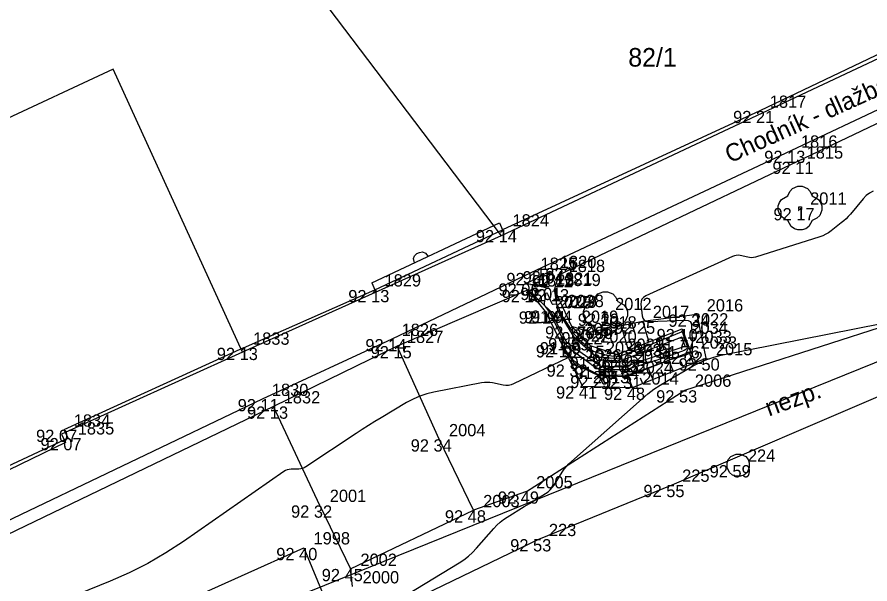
# Model space of a CAD drawing. Extents: x -711081 to -709338, y -1025122 to -1024092.
# Drawn here: x -710758.72 to -710739.27, y -1024920.86 to -1024907.92 of the extents above; entities that cross this region are included whole.
import ezdxf

# ---------------------------------------------------------------- set-up
doc = ezdxf.new("R2010")
doc.units = 0
for name, color, linetype in [('Ex_Major Contours', 7, 'Continuous'), ('Ex_Minor Contours', 7, 'Continuous'), ('Z_betonova_konstrukce', 7, 'Continuous'), ('Z_body', 7, 'Continuous'), ('Z_body_cisla', 7, 'Continuous'), ('Z_body_vysky_redukovane', 7, 'Continuous'), ('Z_budova', 7, 'Continuous'), ('Z_chodnik', 7, 'Continuous'), ('Z_hrany_paty', 7, 'Continuous'), ('Z_katastr_cisla_stavebni', 7, 'Continuous'), ('Z_katastr_hranice', 7, 'Continuous'), ('Z_katastr_vnitrni_kresba', 7, 'Continuous'), ('Z_komunikace', 7, 'Continuous'), ('Z_ploty', 7, 'Continuous'), ('Z_ploty_znacky', 7, 'Continuous'), ('Z_popisy', 7, 'Continuous'), ('Z_rozhranni', 7, 'Continuous'), ('Z_site_kanalizace_znaky', 7, 'Continuous'), ('Z_technicke_srafy', 7, 'Continuous'), ('Z_vstupy', 7, 'Continuous'), ('Z_zelen_jednotliva', 7, 'Continuous'), ('Z_zelen_obvod', 7, 'Continuous'), ('Z_zlabek', 7, 'Continuous')]:
    doc.layers.add(name, color=color, linetype=linetype)

# ---------------------------------------------------------------- blocks, each defined once
blk = doc.blocks.new('POINT_DISPLAY')
blk.add_line((0, 0), (0, 0))
blk = doc.blocks.new('Z24')
for p, q in [((-0.23, 0.38), (-0.17, 0.45)), ((-0.17, 0.45), (-0.05, 0.5)), ((-0.05, 0.5), (0.05, 0.5)), ((0.05, 0.5), (0.17, 0.45)), ((0.17, 0.45), (0.23, 0.38)), ((-0.47, 0.13), (-0.42, 0.2)), ((-0.42, 0.2), (-0.28, 0.28)), ((-0.28, 0.28), (-0.23, 0.38)), ((0.23, 0.38), (0.28, 0.28)), ((0.28, 0.28), (0.42, 0.2)), ((0.42, 0.2), (0.47, 0.13)), ((-0.5, 0.05), (-0.47, 0.13)), ((-0.5, -0.05), (-0.5, 0.05)), ((-0.03, -0.03), (-0.03, 0.03)), ((-0.03, 0.03), (0.03, 0.03)), ((0.03, 0.03), (0.03, -0.03)), ((0.47, 0.13), (0.5, 0.05)), ((0.5, 0.05), (0.5, -0.05)), ((-0.45, -0.17), (-0.5, -0.05)), ((-0.38, -0.23), (-0.45, -0.17)), ((0.03, -0.03), (-0.03, -0.03)), ((0.45, -0.17), (0.38, -0.23)), ((0.5, -0.05), (0.45, -0.17)), ((-0.28, -0.28), (-0.38, -0.23)), ((-0.2, -0.42), (-0.28, -0.28)), ((0.28, -0.28), (0.2, -0.42)), ((0.38, -0.23), (0.28, -0.28)), ((-0.13, -0.47), (-0.2, -0.42)), ((-0.05, -0.5), (-0.13, -0.47)), ((0.05, -0.5), (-0.05, -0.5)), ((0.13, -0.47), (0.05, -0.5)), ((0.2, -0.42), (0.13, -0.47))]:
    blk.add_line(p, q)
blk = doc.blocks.new('Z216')
for p, q in [((-0.17, 0), (-0.15, 0.1)), ((-0.15, 0.1), (-0.1, 0.15)), ((-0.1, 0.15), (-0.03, 0.17)), ((-0.03, 0.17), (0.03, 0.17)), ((0.03, 0.17), (0.1, 0.15)), ((0.1, 0.15), (0.15, 0.1)), ((0.15, 0.1), (0.17, 0))]:
    blk.add_line(p, q)
blk = doc.blocks.new('Z620')
for p, q in [((-0.23, 0.13), (-0.17, 0.2)), ((-0.17, 0.2), (-0.05, 0.25)), ((-0.05, 0.25), (0.05, 0.25)), ((0.05, 0.25), (0.17, 0.2)), ((0.17, 0.2), (0.23, 0.13)), ((-0.25, 0.05), (-0.23, 0.13)), ((-0.25, -0.05), (-0.25, 0.05)), ((0.23, 0.13), (0.25, 0.05)), ((0.25, 0.05), (0.25, -0.05)), ((-0.2, -0.17), (-0.25, -0.05)), ((-0.13, -0.23), (-0.2, -0.17)), ((0.2, -0.17), (0.13, -0.23)), ((0.25, -0.05), (0.2, -0.17)), ((-0.05, -0.25), (-0.13, -0.23)), ((0.05, -0.25), (-0.05, -0.25)), ((0.13, -0.23), (0.05, -0.25))]:
    blk.add_line(p, q)

msp = doc.modelspace()

# ---------------------------------------------------------------- linework, layer by layer
at = {"layer": 'Ex_Major Contours'}
msp.add_lwpolyline([(-710745.611, -1024915.523), (-710745.573, -1024915.546), (-710745.533, -1024915.564), (-710745.491, -1024915.577), (-710745.293, -1024915.629), (-710745.261, -1024915.636), (-710745.23, -1024915.642), (-710745.197, -1024915.647), (-710745.165, -1024915.65), (-710745.036, -1024915.66), (-710745.003, -1024915.66), (-710744.972, -1024915.657), (-710744.941, -1024915.651), (-710744.91, -1024915.641), (-710744.161, -1024915.347), (-710744.1, -1024915.323), (-710744.039, -1024915.299), (-710743.978, -1024915.274), (-710743.917, -1024915.249), (-710743.567, -1024915.104), (-710743.561, -1024915.102), (-710743.555, -1024915.103), (-710743.551, -1024915.106), (-710743.547, -1024915.112), (-710743.535, -1024915.14), (-710743.532, -1024915.148), (-710743.53, -1024915.155), (-710743.527, -1024915.162), (-710743.525, -1024915.169), (-710743.445, -1024915.412), (-710743.438, -1024915.452), (-710743.446, -1024915.484), (-710743.467, -1024915.51), (-710743.502, -1024915.529), (-710743.9, -1024915.676), (-710743.98, -1024915.705), (-710744.061, -1024915.733), (-710744.142, -1024915.76), (-710744.224, -1024915.786), (-710744.789, -1024915.961), (-710744.816, -1024915.969), (-710744.844, -1024915.974), (-710744.871, -1024915.977), (-710744.9, -1024915.977), (-710745.013, -1024915.976), (-710745.041, -1024915.975), (-710745.07, -1024915.975), (-710745.098, -1024915.974), (-710745.126, -1024915.974), (-710745.369, -1024915.972), (-710745.393, -1024915.97), (-710745.416, -1024915.966), (-710745.438, -1024915.959), (-710745.46, -1024915.95), (-710745.545, -1024915.906), (-710745.567, -1024915.895), (-710745.587, -1024915.882), (-710745.607, -1024915.869), (-710745.627, -1024915.855), (-710746.112, -1024915.491), (-710746.125, -1024915.48), (-710746.137, -1024915.469), (-710746.149, -1024915.457), (-710746.16, -1024915.444), (-710746.203, -1024915.393), (-710746.213, -1024915.379), (-710746.222, -1024915.365), (-710746.231, -1024915.351), (-710746.239, -1024915.336), (-710746.459, -1024914.874), (-710746.471, -1024914.85), (-710746.483, -1024914.825), (-710746.496, -1024914.801), (-710746.508, -1024914.777), (-710746.565, -1024914.672), (-710746.576, -1024914.653), (-710746.588, -1024914.634), (-710746.6, -1024914.616), (-710746.613, -1024914.598), (-710746.668, -1024914.528), (-710746.68, -1024914.51), (-710746.687, -1024914.491), (-710746.69, -1024914.47), (-710746.689, -1024914.449), (-710746.657, -1024914.255), (-710746.65, -1024914.225), (-710746.64, -1024914.214), (-710746.628, -1024914.222), (-710746.614, -1024914.25), (-710746.532, -1024914.447), (-710746.526, -1024914.458), (-710746.517, -1024914.465), (-710746.507, -1024914.47), (-710746.494, -1024914.47), (-710746.439, -1024914.467), (-710746.427, -1024914.468), (-710746.416, -1024914.472), (-710746.408, -1024914.48), (-710746.401, -1024914.491), (-710746.333, -1024914.652), (-710746.319, -1024914.682), (-710746.304, -1024914.713), (-710746.287, -1024914.742), (-710746.27, -1024914.771), (-710746.062, -1024915.091), (-710746.044, -1024915.117), (-710746.025, -1024915.142), (-710746.005, -1024915.166), (-710745.984, -1024915.188), (-710745.896, -1024915.277), (-710745.874, -1024915.299), (-710745.851, -1024915.321), (-710745.828, -1024915.342), (-710745.804, -1024915.362), (-710745.646, -1024915.496)], close=True, dxfattribs=at)
at = {"layer": 'Ex_Minor Contours'}
for points in [[(-710739.192, -1024911.897), (-710739.277, -1024911.939), (-710739.353, -1024911.995), (-710739.422, -1024912.066), (-710739.711, -1024912.417), (-710739.759, -1024912.472), (-710739.81, -1024912.524), (-710739.864, -1024912.573), (-710739.92, -1024912.62), (-710740.151, -1024912.801), (-710740.21, -1024912.843), (-710740.272, -1024912.879), (-710740.337, -1024912.91), (-710740.406, -1024912.935), (-710741.88, -1024913.397), (-710741.923, -1024913.407), (-710741.966, -1024913.412), (-710742.01, -1024913.411), (-710742.054, -1024913.404), (-710742.23, -1024913.364), (-710742.273, -1024913.358), (-710742.316, -1024913.359), (-710742.358, -1024913.367), (-710742.4, -1024913.382), (-710744.382, -1024914.287), (-710744.434, -1024914.319), (-710744.469, -1024914.361), (-710744.488, -1024914.413), (-710744.49, -1024914.474), (-710744.463, -1024914.738), (-710744.449, -1024914.795), (-710744.42, -1024914.836), (-710744.376, -1024914.859), (-710744.317, -1024914.866), (-710743.466, -1024914.838), (-710743.41, -1024914.844), (-710743.369, -1024914.867), (-710743.343, -1024914.906), (-710743.334, -1024914.962), (-710743.324, -1024915.29), (-710743.323, -1024915.319), (-710743.323, -1024915.348), (-710743.322, -1024915.376), (-710743.322, -1024915.405), (-710743.322, -1024915.524), (-710743.325, -1024915.548), (-710743.333, -1024915.568), (-710743.348, -1024915.584), (-710743.369, -1024915.596), (-710743.465, -1024915.635), (-710743.489, -1024915.644), (-710743.513, -1024915.653), (-710743.537, -1024915.661), (-710743.562, -1024915.669), (-710743.761, -1024915.726), (-710743.802, -1024915.738), (-710743.843, -1024915.752), (-710743.884, -1024915.765), (-710743.924, -1024915.78), (-710744.628, -1024916.04), (-710744.646, -1024916.047), (-710744.665, -1024916.053), (-710744.684, -1024916.059), (-710744.703, -1024916.065), (-710744.779, -1024916.089), (-710744.798, -1024916.094), (-710744.817, -1024916.098), (-710744.836, -1024916.1), (-710744.856, -1024916.1), (-710745.386, -1024916.092), (-710745.41, -1024916.091), (-710745.433, -1024916.091), (-710745.439, -1024916.091), (-710745.445, -1024916.09), (-710745.451, -1024916.088), (-710745.456, -1024916.085), (-710745.869, -1024915.875), (-710745.885, -1024915.866), (-710745.901, -1024915.856), (-710745.917, -1024915.846), (-710745.932, -1024915.835), (-710745.992, -1024915.79), (-710746.007, -1024915.778), (-710746.021, -1024915.765), (-710746.034, -1024915.752), (-710746.046, -1024915.738), (-710746.124, -1024915.643), (-710746.129, -1024915.638), (-710746.133, -1024915.637), (-710746.135, -1024915.64), (-710746.136, -1024915.647), (-710746.139, -1024915.68), (-710746.14, -1024915.687), (-710746.143, -1024915.694), (-710746.148, -1024915.699), (-710746.155, -1024915.703), (-710747.396, -1024916.296), (-710747.453, -1024916.319), (-710747.512, -1024916.331), (-710747.571, -1024916.333), (-710747.632, -1024916.324), (-710747.878, -1024916.272), (-710747.94, -1024916.262), (-710748.001, -1024916.259), (-710748.063, -1024916.261), (-710748.124, -1024916.27), (-710749.213, -1024916.485), (-710749.376, -1024916.525), (-710749.535, -1024916.578), (-710749.688, -1024916.644), (-710749.836, -1024916.723), (-710750.419, -1024917.067), (-710750.564, -1024917.154), (-710750.708, -1024917.243), (-710750.85, -1024917.333), (-710750.991, -1024917.426), (-710752.133, -1024918.188), (-710752.171, -1024918.21), (-710752.211, -1024918.226), (-710752.252, -1024918.235), (-710752.296, -1024918.239), (-710752.474, -1024918.244), (-710752.518, -1024918.248), (-710752.559, -1024918.258), (-710752.599, -1024918.274), (-710752.636, -1024918.296), (-710754.926, -1024919.89), (-710755.327, -1024920.153), (-710755.74, -1024920.392), (-710756.165, -1024920.607), (-710756.603, -1024920.8), (-710761.026, -1024922.594)], [(-710750.578, -1024921.561), (-710748.641, -1024920.383), (-710748.531, -1024920.31), (-710748.427, -1024920.229), (-710748.33, -1024920.141), (-710748.239, -1024920.045), (-710747.846, -1024919.595), (-710747.778, -1024919.523), (-710747.704, -1024919.455), (-710747.626, -1024919.394), (-710747.543, -1024919.339), (-710747.151, -1024919.097), (-710747.03, -1024919.023), (-710746.909, -1024918.948), (-710746.667, -1024918.799), (-710746.61, -1024918.759), (-710746.558, -1024918.714), (-710746.512, -1024918.662), (-710746.471, -1024918.605), (-710746.285, -1024918.311), (-710746.239, -1024918.243), (-710746.189, -1024918.18), (-710746.134, -1024918.12), (-710746.075, -1024918.064), (-710744.464, -1024916.635), (-710744.331, -1024916.523), (-710744.194, -1024916.418), (-710744.051, -1024916.321), (-710743.903, -1024916.231), (-710743.301, -1024915.883), (-710743.148, -1024915.803), (-710742.99, -1024915.736), (-710742.827, -1024915.683), (-710742.659, -1024915.642), (-710739.003, -1024914.918)]]:
    msp.add_lwpolyline(points, dxfattribs=at)
at = {"layer": 'Z_betonova_konstrukce'}
for p, q in [((-710746.67, -1024914.64), (-710747.06, -1024914.15)), ((-710746.55, -1024914.63), (-710747.06, -1024914.15)), ((-710746.07, -1024914.98), (-710746.46, -1024914.13)), ((-710746.39, -1024914.62), (-710746.46, -1024914.13)), ((-710746.28, -1024915.41), (-710746.67, -1024914.64)), ((-710746.55, -1024914.63), (-710746.19, -1024915.34)), ((-710746, -1024915.25), (-710746.39, -1024914.62)), ((-710746.07, -1024914.98), (-710745.65, -1024915.42)), ((-710745.03, -1024915.62), (-710743.55, -1024915.04)), ((-710743.55, -1024915.04), (-710743.36, -1024915.56)), ((-710745.51, -1024915.68), (-710746, -1024915.25)), ((-710743.56, -1024915.23), (-710744.87, -1024915.74)), ((-710743.48, -1024915.43), (-710743.56, -1024915.23)), ((-710745.99, -1024915.85), (-710746.28, -1024915.41)), ((-710746.19, -1024915.34), (-710745.4, -1024915.9)), ((-710745.65, -1024915.42), (-710745.03, -1024915.62)), ((-710744.86, -1024915.9), (-710743.48, -1024915.43)), ((-710743.36, -1024915.56), (-710744.81, -1024916.13)), ((-710745.45, -1024916.11), (-710745.99, -1024915.85)), ((-710744.87, -1024915.74), (-710745.51, -1024915.68)), ((-710745.4, -1024915.9), (-710744.86, -1024915.9)), ((-710744.81, -1024916.13), (-710745.45, -1024916.11))]:
    msp.add_line(p, q, dxfattribs=at)
at = {"layer": 'Z_budova'}
for p, q in [((-710732.01, -1024905.38), (-710741.78, -1024910.06)), ((-710741.78, -1024910.06), (-710747.65, -1024912.78)), ((-710747.72, -1024912.62), (-710747.65, -1024912.78)), ((-710753.56, -1024915.47), (-710757.66, -1024917.34)), ((-710757.66, -1024917.34), (-710757.56, -1024917.53)), ((-710757.56, -1024917.53), (-710762.28, -1024919.75))]:
    msp.add_line(p, q, dxfattribs=at)
at = {"layer": 'Z_chodnik'}
for p, q in [((-710730.85, -1024906.15), (-710741.07, -1024910.97)), ((-710741.07, -1024910.97), (-710747, -1024913.76)), ((-710747, -1024913.76), (-710750.17, -1024915.27)), ((-710750.17, -1024915.27), (-710753.13, -1024916.64)), ((-710753.13, -1024916.64), (-710761.95, -1024920.86))]:
    msp.add_line(p, q, dxfattribs=at)
at = {"layer": 'Z_hrany_paty'}
for p, q in [((-710747.11, -1024914), (-710746.56, -1024913.72)), ((-710746.56, -1024913.72), (-710746.66, -1024914.1)), ((-710746.66, -1024914.1), (-710747.11, -1024914)), ((-710744.45, -1024914.87), (-710745.65, -1024915.11)), ((-710743.21, -1024914.71), (-710744.45, -1024914.87)), ((-710743, -1024915.71), (-710743.21, -1024914.71)), ((-710745.65, -1024915.11), (-710746.07, -1024914.98)), ((-710745.82, -1024916.35), (-710746.28, -1024915.41)), ((-710744.68, -1024916.38), (-710743, -1024915.71)), ((-710745.82, -1024916.35), (-710744.68, -1024916.38))]:
    msp.add_line(p, q, dxfattribs=at)
at = {"layer": 'Z_katastr_hranice'}
for p, q in [((-710753.31, -1024905.47), (-710747.68, -1024912.91)), ((-710731.99, -1024905.53), (-710747.68, -1024912.91)), ((-710728.9, -1024911.67), (-710760.45, -1024924.43)), ((-710747.68, -1024912.91), (-710753.58, -1024915.57)), ((-710753.58, -1024915.57), (-710757.71, -1024917.44)), ((-710757.71, -1024917.44), (-710757.62, -1024917.63)), ((-710757.62, -1024917.63), (-710762.32, -1024919.91))]:
    msp.add_line(p, q, dxfattribs=at)
at = {"layer": 'Z_katastr_vnitrni_kresba'}
for p, q in [((-710756.53, -1024909.11), (-710760.64, -1024911.02)), ((-710753.58, -1024915.57), (-710756.53, -1024909.11))]:
    msp.add_line(p, q, dxfattribs=at)
at = {"layer": 'Z_komunikace'}
for p, q in [((-710743.78, -1024918.6), (-710733.87, -1024914.34)), ((-710746.82, -1024919.84), (-710743.78, -1024918.6)), ((-710751.3, -1024922), (-710746.82, -1024919.84))]:
    msp.add_line(p, q, dxfattribs=at)
at = {"layer": 'Z_ploty'}
for p, q in [((-710750.63, -1024913.99), (-710747.72, -1024912.62)), ((-710750.56, -1024914.15), (-710747.65, -1024912.78)), ((-710750.63, -1024913.99), (-710750.56, -1024914.15))]:
    msp.add_line(p, q, dxfattribs=at)
at = {"layer": 'Z_rozhranni'}
for p, q in [((-710743.49, -1024916.44), (-710738.41, -1024914.8)), ((-710749.09, -1024917.56), (-710750.05, -1024915.43)), ((-710747.1, -1024918.75), (-710743.49, -1024916.44)), ((-710751.82, -1024919.07), (-710752.87, -1024916.81)), ((-710748.31, -1024919.18), (-710749.09, -1024917.56)), ((-710747.1, -1024918.75), (-710748.31, -1024919.18)), ((-710751.82, -1024919.07), (-710751.12, -1024920.52)), ((-710751.12, -1024920.52), (-710748.31, -1024919.18)), ((-710751.07, -1024920.92), (-710751.12, -1024920.52))]:
    msp.add_line(p, q, dxfattribs=at)
at = {"layer": 'Z_technicke_srafy'}
for p, q in [((-710744.45, -1024914.87), (-710744.31, -1024915.34)), ((-710744.94, -1024914.97), (-710744.78, -1024915.52)), ((-710744.7, -1024914.92), (-710744.62, -1024915.17)), ((-710743.29, -1024915.82), (-710743.39, -1024915.57)), ((-710743.75, -1024916.01), (-710743.85, -1024915.75)), ((-710743.52, -1024915.92), (-710743.57, -1024915.79)), ((-710744.22, -1024916.19), (-710744.32, -1024915.94)), ((-710743.98, -1024916.1), (-710744.03, -1024915.97)), ((-710744.68, -1024916.38), (-710744.78, -1024916.12)), ((-710744.45, -1024916.29), (-710744.5, -1024916.16))]:
    msp.add_line(p, q, dxfattribs=at)
at = {"layer": 'Z_vstupy'}
msp.add_line((-710753.56, -1024915.47), (-710750.56, -1024914.15), dxfattribs=at)
at = {"layer": 'Z_zelen_obvod'}
for p, q in [((-710760.45, -1024923.74), (-710752.18, -1024920.04)), ((-710752.18, -1024920.04), (-710751.69, -1024921.23))]:
    msp.add_line(p, q, dxfattribs=at)
at = {"layer": 'Z_zlabek'}
for p, q in [((-710730.73, -1024906.34), (-710740.93, -1024911.22)), ((-710740.93, -1024911.22), (-710746.37, -1024913.81)), ((-710746.37, -1024913.81), (-710746.46, -1024914.13)), ((-710747.06, -1024914.15), (-710750.05, -1024915.43)), ((-710750.05, -1024915.43), (-710752.87, -1024916.81)), ((-710752.87, -1024916.81), (-710761.84, -1024921.13))]:
    msp.add_line(p, q, dxfattribs=at)

# ---------------------------------------------------------------- block references
at = {"layer": 'Z_body'}
for p in [(-710741.78, -1024910.06), (-710741.07, -1024910.97), (-710740.93, -1024911.22), (-710740.86, -1024912.28), (-710747.65, -1024912.78), (-710747, -1024913.76), (-710746.56, -1024913.72), (-710746.37, -1024913.81), (-710747.11, -1024914), (-710746.66, -1024914.1), (-710750.56, -1024914.15), (-710747.06, -1024914.15), (-710746.46, -1024914.13), (-710746.67, -1024914.64), (-710746.55, -1024914.63), (-710746.39, -1024914.62), (-710745.3, -1024914.69), (-710744.45, -1024914.87), (-710743.21, -1024914.71), (-710746.07, -1024914.98), (-710743.55, -1024915.04), (-710746, -1024915.25), (-710745.65, -1024915.11), (-710743.56, -1024915.23), (-710750.17, -1024915.27), (-710750.05, -1024915.43), (-710746.28, -1024915.41), (-710746.19, -1024915.34), (-710745.65, -1024915.42), (-710743.48, -1024915.43), (-710753.56, -1024915.47), (-710745.03, -1024915.62), (-710743.36, -1024915.56), (-710745.99, -1024915.85), (-710745.51, -1024915.68), (-710744.87, -1024915.74), (-710743, -1024915.71), (-710745.4, -1024915.9), (-710744.86, -1024915.9), (-710745.45, -1024916.11), (-710744.81, -1024916.13), (-710745.82, -1024916.35), (-710744.68, -1024916.38), (-710743.49, -1024916.44), (-710753.13, -1024916.64), (-710752.87, -1024916.81), (-710757.66, -1024917.34), (-710757.56, -1024917.53), (-710749.09, -1024917.56), (-710742.27, -1024918.15), (-710747.1, -1024918.75), (-710743.78, -1024918.6), (-710751.82, -1024919.07), (-710748.31, -1024919.18), (-710746.82, -1024919.84), (-710752.18, -1024920.04), (-710751.12, -1024920.52)]:
    msp.add_blockref('POINT_DISPLAY', p, dxfattribs=at)
at = {"layer": 'Z_ploty_znacky', "rotation": 25.200000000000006}
msp.add_blockref('Z216', (-710749.5, -1024913.46), dxfattribs=at)
at = {"layer": 'Z_site_kanalizace_znaky'}
msp.add_blockref('Z620', (-710742.27, -1024918.15), dxfattribs=at)
at = {"layer": 'Z_zelen_jednotliva'}
for p in [(-710740.86, -1024912.28), (-710745.3, -1024914.69)]:
    msp.add_blockref('Z24', p, dxfattribs=at)

# ---------------------------------------------------------------- texts
at = {"layer": 'Z_body_cisla'}
for s, p in [('1817', (-710741.55, -1024909.99)), ('1816', (-710740.84, -1024910.9)), ('1815', (-710740.71, -1024911.15)), ('2011', (-710740.63, -1024912.2)), ('1824', (-710747.42, -1024912.7)), ('1825', (-710746.78, -1024913.69)), ('1820', (-710746.34, -1024913.65)), ('1818', (-710746.14, -1024913.74)), ('1822', (-710746.88, -1024913.93)), ('1829', (-710750.34, -1024914.07)), ('1823', (-710746.84, -1024914.07)), ('1821', (-710746.43, -1024914.03)), ('1819', (-710746.24, -1024914.06)), ('2028', (-710746.45, -1024914.57)), ('2029', (-710746.33, -1024914.56)), ('2038', (-710746.17, -1024914.54)), ('2012', (-710745.08, -1024914.61)), ('2016', (-710742.99, -1024914.64)), ('2019', (-710745.84, -1024914.9)), ('2017', (-710744.22, -1024914.79)), ('2022', (-710743.33, -1024914.96)), ('2018', (-710745.42, -1024915.03)), ('2034', (-710743.34, -1024915.15)), ('1826', (-710749.95, -1024915.2)), ('2027', (-710746.05, -1024915.33)), ('2030', (-710745.96, -1024915.27)), ('2037', (-710745.78, -1024915.18)), ('2020', (-710745.42, -1024915.35)), ('1833', (-710753.34, -1024915.4)), ('1827', (-710749.83, -1024915.36)), ('2021', (-710744.8, -1024915.54)), ('2033', (-710743.25, -1024915.36)), ('2023', (-710743.13, -1024915.49)), ('2036', (-710745.29, -1024915.61)), ('2035', (-710744.64, -1024915.66)), ('2015', (-710742.78, -1024915.64)), ('2026', (-710745.76, -1024915.78)), ('2031', (-710745.17, -1024915.82)), ('2032', (-710744.63, -1024915.82)), ('2025', (-710745.22, -1024916.03)), ('2024', (-710744.59, -1024916.06)), ('2013', (-710745.59, -1024916.28)), ('2014', (-710744.46, -1024916.31)), ('2006', (-710743.26, -1024916.36)), ('1830', (-710752.91, -1024916.57)), ('1832', (-710752.64, -1024916.74)), ('1834', (-710757.43, -1024917.27)), ('1835', (-710757.34, -1024917.45)), ('2004', (-710748.87, -1024917.49)), ('224', (-710742.05, -1024918.07)), ('225', (-710743.55, -1024918.53)), ('2005', (-710746.88, -1024918.68)), ('2001', (-710751.59, -1024918.99)), ('2003', (-710748.09, -1024919.11)), ('223', (-710746.59, -1024919.77)), ('1998', (-710751.96, -1024919.96)), ('2002', (-710750.89, -1024920.45)), ('2000', (-710750.84, -1024920.85))]:
    msp.add_text(s, height=0.28, dxfattribs=at).set_placement(p)
at = {"layer": 'Z_body_vysky_redukovane'}
for s, p in [('92 21', (-710742.387, -1024910.34)), ('92 13', (-710741.677, -1024911.25)), ('92 11', (-710741.49, -1024911.5)), ('92 17', (-710741.467, -1024912.56)), ('92 14', (-710748.257, -1024913.06)), ('92 11', (-710747.56, -1024914.04)), ('92 04', (-710747.19, -1024914)), ('92 12', (-710746.977, -1024914.09)), ('92 06', (-710747.74, -1024914.28)), ('92 01', (-710747.243, -1024914.38)), ('92 13', (-710751.167, -1024914.43)), ('92 15', (-710747.667, -1024914.43)), ('92 13', (-710747.067, -1024914.41)), ('92 14', (-710747.277, -1024914.92)), ('91 94', (-710747.157, -1024914.91)), ('91 94', (-710746.997, -1024914.9)), ('92 20', (-710745.93, -1024914.97)), ('92 25', (-710745.103, -1024915.15)), ('92 34', (-710743.863, -1024914.99)), ('92 17', (-710746.677, -1024915.26)), ('92 10', (-710744.133, -1024915.32)), ('92 14', (-710750.777, -1024915.55)), ('91 89', (-710746.607, -1024915.53)), ('92 22', (-710746.303, -1024915.39)), ('91 77', (-710744.167, -1024915.51)), ('92 15', (-710750.657, -1024915.71)), ('92 18', (-710746.887, -1024915.69)), ('91 89', (-710746.797, -1024915.62)), ('92 15', (-710746.257, -1024915.7)), ('91 76', (-710744.087, -1024915.71)), ('92 13', (-710754.167, -1024915.75)), ('92 10', (-710745.613, -1024915.9)), ('92 22', (-710744.013, -1024915.84)), ('92 32', (-710746.643, -1024916.13)), ('91 86', (-710746.117, -1024915.96)), ('91 83', (-710745.477, -1024916.02)), ('92 50', (-710743.63, -1024915.99)), ('91 85', (-710746.007, -1024916.18)), ('91 84', (-710745.467, -1024916.18)), ('92 29', (-710746.103, -1024916.39)), ('92 31', (-710745.417, -1024916.41)), ('92 41', (-710746.427, -1024916.63)), ('92 48', (-710745.333, -1024916.66)), ('92 53', (-710744.143, -1024916.72)), ('92 11', (-710753.69, -1024916.92)), ('92 13', (-710753.477, -1024917.09)), ('92 07', (-710758.29, -1024917.62)), ('92 07', (-710758.19, -1024917.81)), ('92 34', (-710749.743, -1024917.84)), ('92 59', (-710742.923, -1024918.43)), ('92 49', (-710747.753, -1024919.03)), ('92 55', (-710744.433, -1024918.88)), ('92 32', (-710752.473, -1024919.35)), ('92 48', (-710748.963, -1024919.46)), ('92 53', (-710747.473, -1024920.12)), ('92 40', (-710752.81, -1024920.32)), ('92 45', (-710751.773, -1024920.8))]:
    msp.add_text(s, height=0.28, dxfattribs=at).set_placement(p)
at = {"layer": 'Z_katastr_cisla_stavebni'}
msp.add_text('82/1', height=0.425, dxfattribs=at).set_placement((-710744.779, -1024909.049))
at = {"layer": 'Z_popisy'}
for s, rotation, p in [('Chodník - dlažba', 24.3, (-710742.46, -1024911.26)), ('nezp.', 19.8, (-710741.57, -1024917.04))]:
    msp.add_text(s, height=0.4, rotation=rotation, dxfattribs=at).set_placement(p)

doc.saveas('drawing.dxf')
